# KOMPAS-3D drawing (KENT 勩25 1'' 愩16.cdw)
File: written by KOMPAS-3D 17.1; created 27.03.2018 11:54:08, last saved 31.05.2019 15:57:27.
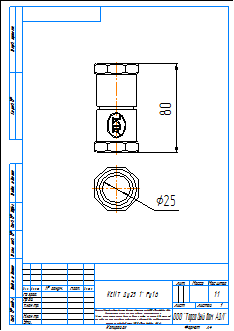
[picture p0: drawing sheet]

Sheet 1: A4, portrait

Title block, sheet 1: name: KENT Ду25 1'' Ру16; material: Внимание! Данный продукт является объектом авторского права ООО «Торговый Дом АДЛ». / Запрещается изменение, копирование, распространение / (в том числе путем копирования на другие сайты и ресурсы в Интернете) / или любое иное использование информации и объектов без предварительного / согласия правообладателя (ООО «Торговый Дом АДЛ»).; sheets: 1; organisation: ООО "Торговый дом АДЛ"; sheet format: A4; stored path: \\adlc.lan\data\АДЛ_ПКД\3D-модели\Поставщики\Standard Hidraulica\Латунный обратный клапан KENT PN16\KOMPAS 2D\KENT Ду25 1'' Ру16.cdw

Views: Вид 1, Проекционный вид 2
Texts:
  kka
  adl
Dimensions and other numbers on the sheet: 80; 25; 1:1; 1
